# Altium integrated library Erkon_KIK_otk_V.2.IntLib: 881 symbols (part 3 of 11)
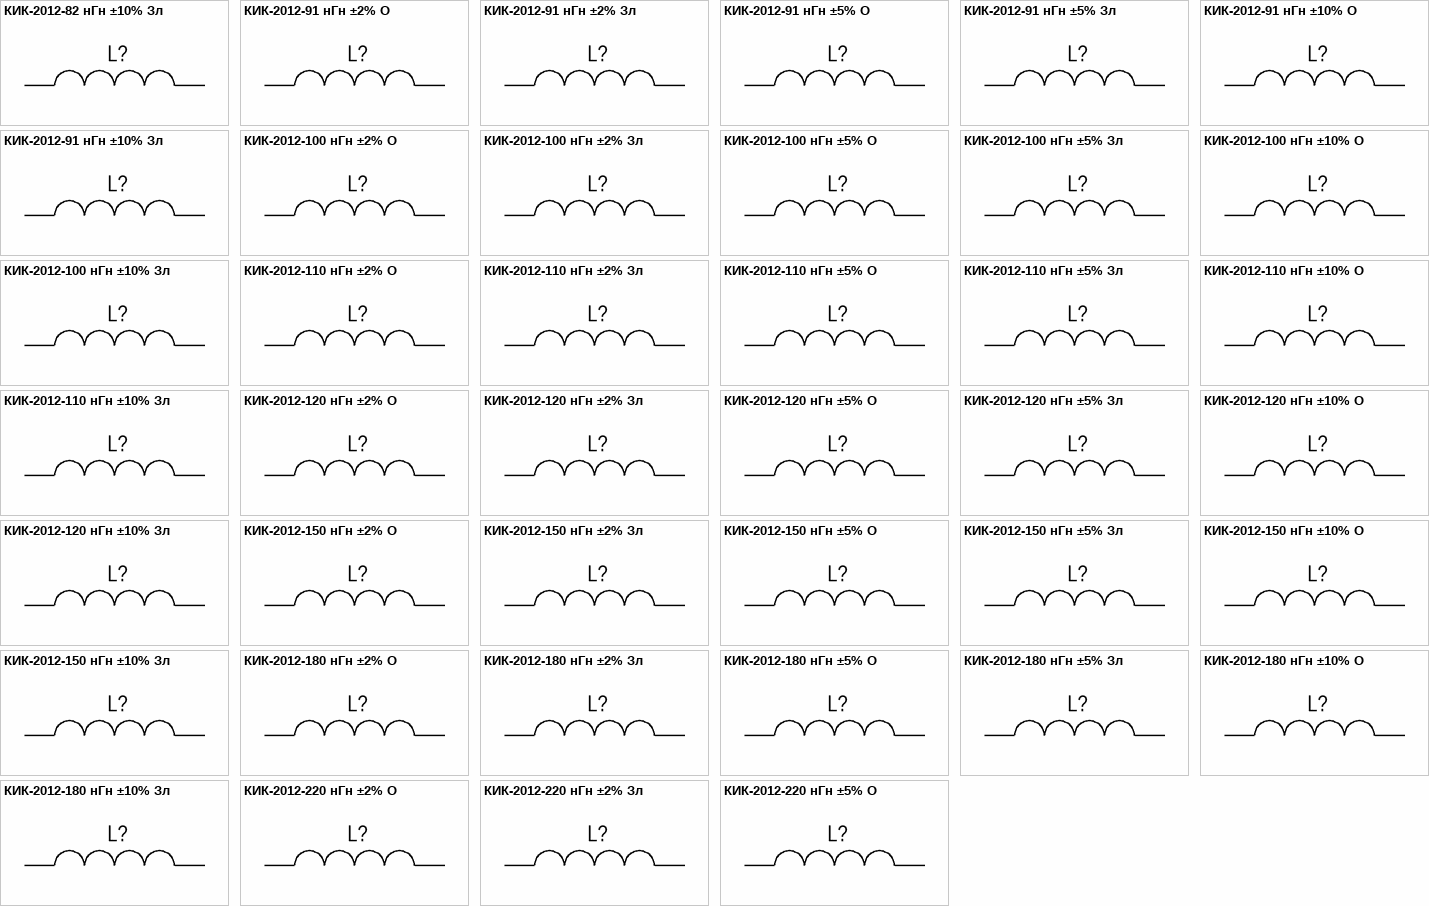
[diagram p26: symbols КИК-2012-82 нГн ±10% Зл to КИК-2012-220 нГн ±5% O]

## КИК-2012-220 нГн ±2% Зл
designator L?, comment 220 нГн ±2%  (value not drawn)
Катушка индуктивности с керамическим сердечником и золотым покрытием контактных площадок; Номиналиная индуктивность: 220 нГн; Добротность, не менее: 50; Резонансная частота, не менее: 0.82 ГГц; Сопротивление обмотки постоянноми току, не более: 0.70 Ом; Допустимый ток обмотки: 400 мА; Диапазон рабочих температур: от -60 до +125 ℃; Упаковка: Катушка и лента; Типоразмер: 2012 (0805); Технология монтажа: SMT; Изготовитель: АО "НПО "ЭРКОН"
footprint КИК-2012-Зл (Катушка индуктивности с керамическим сердечникомтипоразмер 2012(0805))
pins: 1, 2

## КИК-2012-220 нГн ±5% O
designator L?, comment 220 нГн ±5%  (value not drawn)
Катушка индуктивности с керамическим сердечником и  финишным покрытием контактных площадок оловом; Номиналиная индуктивность: 220 нГн; Добротность, не менее: 50; Резонансная частота, не менее: 0.82 ГГц; Сопротивление обмотки постоянноми току, не более: 0.70 Ом; Допустимый ток обмотки: 400 мА; Диапазон рабочих температур: от -60 до +125 ℃; Упаковка: Катушка и лента; Типоразмер: 2012 (0805); Технология монтажа: SMT; Изготовитель: АО "НПО "ЭРКОН"
footprint КИК-2012-O (Катушка индуктивности с керамическим сердечником типоразмер 2012(0805))
pins: 1, 2

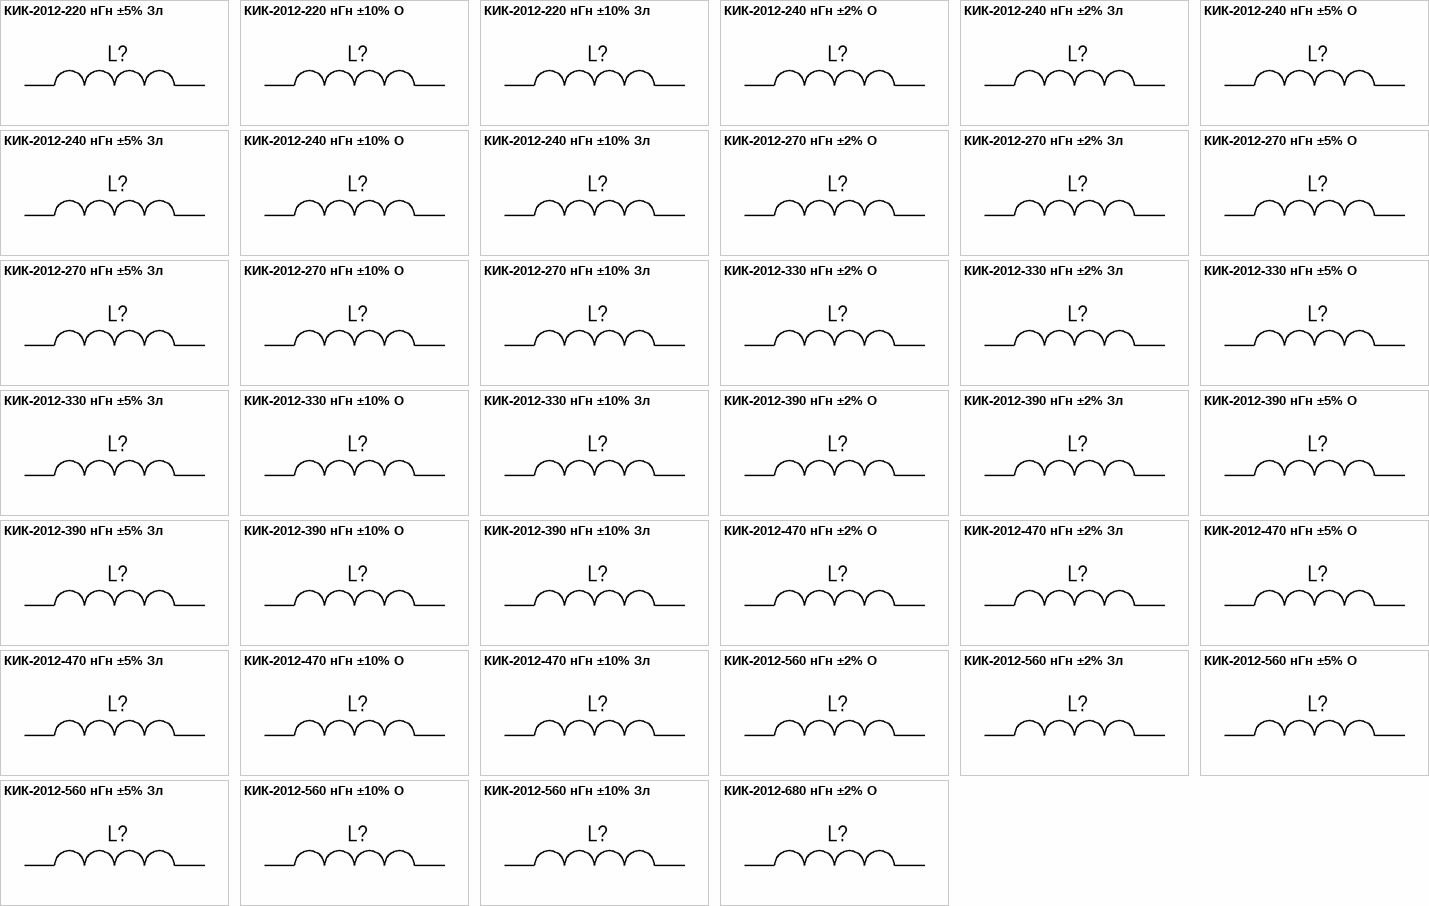
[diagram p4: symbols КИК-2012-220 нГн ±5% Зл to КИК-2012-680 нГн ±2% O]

## КИК-2012-220 нГн ±5% Зл
designator L?, comment 220 нГн ±5%  (value not drawn)
Катушка индуктивности с керамическим сердечником и золотым покрытием контактных площадок; Номиналиная индуктивность: 220 нГн; Добротность, не менее: 50; Резонансная частота, не менее: 0.82 ГГц; Сопротивление обмотки постоянноми току, не более: 0.70 Ом; Допустимый ток обмотки: 400 мА; Диапазон рабочих температур: от -60 до +125 ℃; Упаковка: Катушка и лента; Типоразмер: 2012 (0805); Технология монтажа: SMT; Изготовитель: АО "НПО "ЭРКОН"
footprint КИК-2012-Зл (Катушка индуктивности с керамическим сердечникомтипоразмер 2012(0805))
pins: 1, 2

## КИК-2012-220 нГн ±10% O
designator L?, comment 220 нГн ±10%  (value not drawn)
Катушка индуктивности с керамическим сердечником и  финишным покрытием контактных площадок оловом; Номиналиная индуктивность: 220 нГн; Добротность, не менее: 50; Резонансная частота, не менее: 0.82 ГГц; Сопротивление обмотки постоянноми току, не более: 0.70 Ом; Допустимый ток обмотки: 400 мА; Диапазон рабочих температур: от -60 до +125 ℃; Упаковка: Катушка и лента; Типоразмер: 2012 (0805); Технология монтажа: SMT; Изготовитель: АО "НПО "ЭРКОН"
footprint КИК-2012-O (Катушка индуктивности с керамическим сердечником типоразмер 2012(0805))
pins: 1, 2

## КИК-2012-220 нГн ±10% Зл
designator L?, comment 220 нГн ±10%  (value not drawn)
Катушка индуктивности с керамическим сердечником и золотым покрытием контактных площадок; Номиналиная индуктивность: 220 нГн; Добротность, не менее: 50; Резонансная частота, не менее: 0.82 ГГц; Сопротивление обмотки постоянноми току, не более: 0.70 Ом; Допустимый ток обмотки: 400 мА; Диапазон рабочих температур: от -60 до +125 ℃; Упаковка: Катушка и лента; Типоразмер: 2012 (0805); Технология монтажа: SMT; Изготовитель: АО "НПО "ЭРКОН"
footprint КИК-2012-Зл (Катушка индуктивности с керамическим сердечникомтипоразмер 2012(0805))
pins: 1, 2

## КИК-2012-240 нГн ±2% O
designator L?, comment 240 нГн ±2%  (value not drawn)
Катушка индуктивности с керамическим сердечником и  финишным покрытием контактных площадок оловом; Номиналиная индуктивность: 240 нГн; Добротность, не менее: 45; Резонансная частота, не менее: 0.77 ГГц; Сопротивление обмотки постоянноми току, не более: 1.0 Ом; Допустимый ток обмотки: 350 мА; Диапазон рабочих температур: от -60 до +125 ℃; Упаковка: Катушка и лента; Типоразмер: 2012 (0805); Технология монтажа: SMT; Изготовитель: АО "НПО "ЭРКОН"
footprint КИК-2012-O (Катушка индуктивности с керамическим сердечником типоразмер 2012(0805))
pins: 1, 2

## КИК-2012-240 нГн ±2% Зл
designator L?, comment 240 нГн ±2%  (value not drawn)
Катушка индуктивности с керамическим сердечником и золотым покрытием контактных площадок; Номиналиная индуктивность: 240 нГн; Добротность, не менее: 45; Резонансная частота, не менее: 0.77 ГГц; Сопротивление обмотки постоянноми току, не более: 1.0 Ом; Допустимый ток обмотки: 350 мА; Диапазон рабочих температур: от -60 до +125 ℃; Упаковка: Катушка и лента; Типоразмер: 2012 (0805); Технология монтажа: SMT; Изготовитель: АО "НПО "ЭРКОН"
footprint КИК-2012-Зл (Катушка индуктивности с керамическим сердечникомтипоразмер 2012(0805))
pins: 1, 2

## КИК-2012-240 нГн ±5% O
designator L?, comment 240 нГн ±5%  (value not drawn)
Катушка индуктивности с керамическим сердечником и  финишным покрытием контактных площадок оловом; Номиналиная индуктивность: 240 нГн; Добротность, не менее: 45; Резонансная частота, не менее: 0.77 ГГц; Сопротивление обмотки постоянноми току, не более: 1.0 Ом; Допустимый ток обмотки: 350 мА; Диапазон рабочих температур: от -60 до +125 ℃; Упаковка: Катушка и лента; Типоразмер: 2012 (0805); Технология монтажа: SMT; Изготовитель: АО "НПО "ЭРКОН"
footprint КИК-2012-O (Катушка индуктивности с керамическим сердечником типоразмер 2012(0805))
pins: 1, 2

## КИК-2012-240 нГн ±5% Зл
designator L?, comment 240 нГн ±5%  (value not drawn)
Катушка индуктивности с керамическим сердечником и золотым покрытием контактных площадок; Номиналиная индуктивность: 240 нГн; Добротность, не менее: 45; Резонансная частота, не менее: 0.77 ГГц; Сопротивление обмотки постоянноми току, не более: 1.0 Ом; Допустимый ток обмотки: 350 мА; Диапазон рабочих температур: от -60 до +125 ℃; Упаковка: Катушка и лента; Типоразмер: 2012 (0805); Технология монтажа: SMT; Изготовитель: АО "НПО "ЭРКОН"
footprint КИК-2012-Зл (Катушка индуктивности с керамическим сердечникомтипоразмер 2012(0805))
pins: 1, 2

## КИК-2012-240 нГн ±10% O
designator L?, comment 240 нГн ±10%  (value not drawn)
Катушка индуктивности с керамическим сердечником и  финишным покрытием контактных площадок оловом; Номиналиная индуктивность: 240 нГн; Добротность, не менее: 45; Резонансная частота, не менее: 0.77 ГГц; Сопротивление обмотки постоянноми току, не более: 1.0 Ом; Допустимый ток обмотки: 350 мА; Диапазон рабочих температур: от -60 до +125 ℃; Упаковка: Катушка и лента; Типоразмер: 2012 (0805); Технология монтажа: SMT; Изготовитель: АО "НПО "ЭРКОН"
footprint КИК-2012-O (Катушка индуктивности с керамическим сердечником типоразмер 2012(0805))
pins: 1, 2

## КИК-2012-240 нГн ±10% Зл
designator L?, comment 240 нГн ±10%  (value not drawn)
Катушка индуктивности с керамическим сердечником и золотым покрытием контактных площадок; Номиналиная индуктивность: 240 нГн; Добротность, не менее: 45; Резонансная частота, не менее: 0.77 ГГц; Сопротивление обмотки постоянноми току, не более: 1.0 Ом; Допустимый ток обмотки: 350 мА; Диапазон рабочих температур: от -60 до +125 ℃; Упаковка: Катушка и лента; Типоразмер: 2012 (0805); Технология монтажа: SMT; Изготовитель: АО "НПО "ЭРКОН"
footprint КИК-2012-Зл (Катушка индуктивности с керамическим сердечникомтипоразмер 2012(0805))
pins: 1, 2

## КИК-2012-270 нГн ±2% O
designator L?, comment 270 нГн ±2%  (value not drawn)
Катушка индуктивности с керамическим сердечником и  финишным покрытием контактных площадок оловом; Номиналиная индуктивность: 270 нГн; Добротность, не менее: 45; Резонансная частота, не менее: 0.73 ГГц; Сопротивление обмотки постоянноми току, не более: 1.0 Ом; Допустимый ток обмотки: 350 мА; Диапазон рабочих температур: от -60 до +125 ℃; Упаковка: Катушка и лента; Типоразмер: 2012 (0805); Технология монтажа: SMT; Изготовитель: АО "НПО "ЭРКОН"
footprint КИК-2012-O (Катушка индуктивности с керамическим сердечником типоразмер 2012(0805))
pins: 1, 2

## КИК-2012-270 нГн ±2% Зл
designator L?, comment 270 нГн ±2%  (value not drawn)
Катушка индуктивности с керамическим сердечником и золотым покрытием контактных площадок; Номиналиная индуктивность: 270 нГн; Добротность, не менее: 45; Резонансная частота, не менее: 0.73 ГГц; Сопротивление обмотки постоянноми току, не более: 1.0 Ом; Допустимый ток обмотки: 350 мА; Диапазон рабочих температур: от -60 до +125 ℃; Упаковка: Катушка и лента; Типоразмер: 2012 (0805); Технология монтажа: SMT; Изготовитель: АО "НПО "ЭРКОН"
footprint КИК-2012-Зл (Катушка индуктивности с керамическим сердечникомтипоразмер 2012(0805))
pins: 1, 2

## КИК-2012-270 нГн ±5% O
designator L?, comment 270 нГн ±5%  (value not drawn)
Катушка индуктивности с керамическим сердечником и  финишным покрытием контактных площадок оловом; Номиналиная индуктивность: 270 нГн; Добротность, не менее: 45; Резонансная частота, не менее: 0.73 ГГц; Сопротивление обмотки постоянноми току, не более: 1.0 Ом; Допустимый ток обмотки: 350 мА; Диапазон рабочих температур: от -60 до +125 ℃; Упаковка: Катушка и лента; Типоразмер: 2012 (0805); Технология монтажа: SMT; Изготовитель: АО "НПО "ЭРКОН"
footprint КИК-2012-O (Катушка индуктивности с керамическим сердечником типоразмер 2012(0805))
pins: 1, 2

## КИК-2012-270 нГн ±5% Зл
designator L?, comment 270 нГн ±5%  (value not drawn)
Катушка индуктивности с керамическим сердечником и золотым покрытием контактных площадок; Номиналиная индуктивность: 270 нГн; Добротность, не менее: 45; Резонансная частота, не менее: 0.73 ГГц; Сопротивление обмотки постоянноми току, не более: 1.0 Ом; Допустимый ток обмотки: 350 мА; Диапазон рабочих температур: от -60 до +125 ℃; Упаковка: Катушка и лента; Типоразмер: 2012 (0805); Технология монтажа: SMT; Изготовитель: АО "НПО "ЭРКОН"
footprint КИК-2012-Зл (Катушка индуктивности с керамическим сердечникомтипоразмер 2012(0805))
pins: 1, 2

## КИК-2012-270 нГн ±10% O
designator L?, comment 270 нГн ±10%  (value not drawn)
Катушка индуктивности с керамическим сердечником и  финишным покрытием контактных площадок оловом; Номиналиная индуктивность: 270 нГн; Добротность, не менее: 45; Резонансная частота, не менее: 0.73 ГГц; Сопротивление обмотки постоянноми току, не более: 1.0 Ом; Допустимый ток обмотки: 350 мА; Диапазон рабочих температур: от -60 до +125 ℃; Упаковка: Катушка и лента; Типоразмер: 2012 (0805); Технология монтажа: SMT; Изготовитель: АО "НПО "ЭРКОН"
footprint КИК-2012-O (Катушка индуктивности с керамическим сердечником типоразмер 2012(0805))
pins: 1, 2

## КИК-2012-270 нГн ±10% Зл
designator L?, comment 270 нГн ±10%  (value not drawn)
Катушка индуктивности с керамическим сердечником и золотым покрытием контактных площадок; Номиналиная индуктивность: 270 нГн; Добротность, не менее: 45; Резонансная частота, не менее: 0.73 ГГц; Сопротивление обмотки постоянноми току, не более: 1.0 Ом; Допустимый ток обмотки: 350 мА; Диапазон рабочих температур: от -60 до +125 ℃; Упаковка: Катушка и лента; Типоразмер: 2012 (0805); Технология монтажа: SMT; Изготовитель: АО "НПО "ЭРКОН"
footprint КИК-2012-Зл (Катушка индуктивности с керамическим сердечникомтипоразмер 2012(0805))
pins: 1, 2

## КИК-2012-330 нГн ±2% O
designator L?, comment 330 нГн ±2%  (value not drawn)
Катушка индуктивности с керамическим сердечником и  финишным покрытием контактных площадок оловом; Номиналиная индуктивность: 330 нГн; Добротность, не менее: 45; Резонансная частота, не менее: 0.65 ГГц; Сопротивление обмотки постоянноми току, не более: 1.4 Ом; Допустимый ток обмотки: 310 мА; Диапазон рабочих температур: от -60 до +125 ℃; Упаковка: Катушка и лента; Типоразмер: 2012 (0805); Технология монтажа: SMT; Изготовитель: АО "НПО "ЭРКОН"
footprint КИК-2012-O (Катушка индуктивности с керамическим сердечником типоразмер 2012(0805))
pins: 1, 2

## КИК-2012-330 нГн ±2% Зл
designator L?, comment 330 нГн ±2%  (value not drawn)
Катушка индуктивности с керамическим сердечником и золотым покрытием контактных площадок; Номиналиная индуктивность: 330 нГн; Добротность, не менее: 45; Резонансная частота, не менее: 0.65 ГГц; Сопротивление обмотки постоянноми току, не более: 1.4 Ом; Допустимый ток обмотки: 310 мА; Диапазон рабочих температур: от -60 до +125 ℃; Упаковка: Катушка и лента; Типоразмер: 2012 (0805); Технология монтажа: SMT; Изготовитель: АО "НПО "ЭРКОН"
footprint КИК-2012-Зл (Катушка индуктивности с керамическим сердечникомтипоразмер 2012(0805))
pins: 1, 2

## КИК-2012-330 нГн ±5% O
designator L?, comment 330 нГн ±5%  (value not drawn)
Катушка индуктивности с керамическим сердечником и  финишным покрытием контактных площадок оловом; Номиналиная индуктивность: 330 нГн; Добротность, не менее: 45; Резонансная частота, не менее: 0.65 ГГц; Сопротивление обмотки постоянноми току, не более: 1.4 Ом; Допустимый ток обмотки: 310 мА; Диапазон рабочих температур: от -60 до +125 ℃; Упаковка: Катушка и лента; Типоразмер: 2012 (0805); Технология монтажа: SMT; Изготовитель: АО "НПО "ЭРКОН"
footprint КИК-2012-O (Катушка индуктивности с керамическим сердечником типоразмер 2012(0805))
pins: 1, 2

## КИК-2012-330 нГн ±5% Зл
designator L?, comment 330 нГн ±5%  (value not drawn)
Катушка индуктивности с керамическим сердечником и золотым покрытием контактных площадок; Номиналиная индуктивность: 330 нГн; Добротность, не менее: 45; Резонансная частота, не менее: 0.65 ГГц; Сопротивление обмотки постоянноми току, не более: 1.4 Ом; Допустимый ток обмотки: 310 мА; Диапазон рабочих температур: от -60 до +125 ℃; Упаковка: Катушка и лента; Типоразмер: 2012 (0805); Технология монтажа: SMT; Изготовитель: АО "НПО "ЭРКОН"
footprint КИК-2012-Зл (Катушка индуктивности с керамическим сердечникомтипоразмер 2012(0805))
pins: 1, 2

## КИК-2012-330 нГн ±10% O
designator L?, comment 330 нГн ±10%  (value not drawn)
Катушка индуктивности с керамическим сердечником и  финишным покрытием контактных площадок оловом; Номиналиная индуктивность: 330 нГн; Добротность, не менее: 45; Резонансная частота, не менее: 0.65 ГГц; Сопротивление обмотки постоянноми току, не более: 1.4 Ом; Допустимый ток обмотки: 310 мА; Диапазон рабочих температур: от -60 до +125 ℃; Упаковка: Катушка и лента; Типоразмер: 2012 (0805); Технология монтажа: SMT; Изготовитель: АО "НПО "ЭРКОН"
footprint КИК-2012-O (Катушка индуктивности с керамическим сердечником типоразмер 2012(0805))
pins: 1, 2

## КИК-2012-330 нГн ±10% Зл
designator L?, comment 330 нГн ±10%  (value not drawn)
Катушка индуктивности с керамическим сердечником и золотым покрытием контактных площадок; Номиналиная индуктивность: 330 нГн; Добротность, не менее: 45; Резонансная частота, не менее: 0.65 ГГц; Сопротивление обмотки постоянноми току, не более: 1.4 Ом; Допустимый ток обмотки: 310 мА; Диапазон рабочих температур: от -60 до +125 ℃; Упаковка: Катушка и лента; Типоразмер: 2012 (0805); Технология монтажа: SMT; Изготовитель: АО "НПО "ЭРКОН"
footprint КИК-2012-Зл (Катушка индуктивности с керамическим сердечникомтипоразмер 2012(0805))
pins: 1, 2

## КИК-2012-390 нГн ±2% O
designator L?, comment 390 нГн ±2%  (value not drawn)
Катушка индуктивности с керамическим сердечником и  финишным покрытием контактных площадок оловом; Номиналиная индуктивность: 390 нГн; Добротность, не менее: 45; Резонансная частота, не менее: 0.60 ГГц; Сопротивление обмотки постоянноми току, не более: 1.5 Ом; Допустимый ток обмотки: 290 мА; Диапазон рабочих температур: от -60 до +125 ℃; Упаковка: Катушка и лента; Типоразмер: 2012 (0805); Технология монтажа: SMT; Изготовитель: АО "НПО "ЭРКОН"
footprint КИК-2012-O (Катушка индуктивности с керамическим сердечником типоразмер 2012(0805))
pins: 1, 2

## КИК-2012-390 нГн ±2% Зл
designator L?, comment 390 нГн ±2%  (value not drawn)
Катушка индуктивности с керамическим сердечником и золотым покрытием контактных площадок; Номиналиная индуктивность: 390 нГн; Добротность, не менее: 45; Резонансная частота, не менее: 0.60 ГГц; Сопротивление обмотки постоянноми току, не более: 1.5 Ом; Допустимый ток обмотки: 290 мА; Диапазон рабочих температур: от -60 до +125 ℃; Упаковка: Катушка и лента; Типоразмер: 2012 (0805); Технология монтажа: SMT; Изготовитель: АО "НПО "ЭРКОН"
footprint КИК-2012-Зл (Катушка индуктивности с керамическим сердечникомтипоразмер 2012(0805))
pins: 1, 2

## КИК-2012-390 нГн ±5% O
designator L?, comment 390 нГн ±5%  (value not drawn)
Катушка индуктивности с керамическим сердечником и  финишным покрытием контактных площадок оловом; Номиналиная индуктивность: 390 нГн; Добротность, не менее: 45; Резонансная частота, не менее: 0.60 ГГц; Сопротивление обмотки постоянноми току, не более: 1.5 Ом; Допустимый ток обмотки: 290 мА; Диапазон рабочих температур: от -60 до +125 ℃; Упаковка: Катушка и лента; Типоразмер: 2012 (0805); Технология монтажа: SMT; Изготовитель: АО "НПО "ЭРКОН"
footprint КИК-2012-O (Катушка индуктивности с керамическим сердечником типоразмер 2012(0805))
pins: 1, 2

## КИК-2012-390 нГн ±5% Зл
designator L?, comment 390 нГн ±5%  (value not drawn)
Катушка индуктивности с керамическим сердечником и золотым покрытием контактных площадок; Номиналиная индуктивность: 390 нГн; Добротность, не менее: 45; Резонансная частота, не менее: 0.60 ГГц; Сопротивление обмотки постоянноми току, не более: 1.5 Ом; Допустимый ток обмотки: 290 мА; Диапазон рабочих температур: от -60 до +125 ℃; Упаковка: Катушка и лента; Типоразмер: 2012 (0805); Технология монтажа: SMT; Изготовитель: АО "НПО "ЭРКОН"
footprint КИК-2012-Зл (Катушка индуктивности с керамическим сердечникомтипоразмер 2012(0805))
pins: 1, 2

## КИК-2012-390 нГн ±10% O
designator L?, comment 390 нГн ±10%  (value not drawn)
Катушка индуктивности с керамическим сердечником и  финишным покрытием контактных площадок оловом; Номиналиная индуктивность: 390 нГн; Добротность, не менее: 45; Резонансная частота, не менее: 0.60 ГГц; Сопротивление обмотки постоянноми току, не более: 1.5 Ом; Допустимый ток обмотки: 290 мА; Диапазон рабочих температур: от -60 до +125 ℃; Упаковка: Катушка и лента; Типоразмер: 2012 (0805); Технология монтажа: SMT; Изготовитель: АО "НПО "ЭРКОН"
footprint КИК-2012-O (Катушка индуктивности с керамическим сердечником типоразмер 2012(0805))
pins: 1, 2

## КИК-2012-390 нГн ±10% Зл
designator L?, comment 390 нГн ±10%  (value not drawn)
Катушка индуктивности с керамическим сердечником и золотым покрытием контактных площадок; Номиналиная индуктивность: 390 нГн; Добротность, не менее: 45; Резонансная частота, не менее: 0.60 ГГц; Сопротивление обмотки постоянноми току, не более: 1.5 Ом; Допустимый ток обмотки: 290 мА; Диапазон рабочих температур: от -60 до +125 ℃; Упаковка: Катушка и лента; Типоразмер: 2012 (0805); Технология монтажа: SMT; Изготовитель: АО "НПО "ЭРКОН"
footprint КИК-2012-Зл (Катушка индуктивности с керамическим сердечникомтипоразмер 2012(0805))
pins: 1, 2

## КИК-2012-470 нГн ±2% O
designator L?, comment 470 нГн ±2%  (value not drawn)
Катушка индуктивности с керамическим сердечником и  финишным покрытием контактных площадок оловом; Номиналиная индуктивность: 470 нГн; Добротность, не менее: 33; Резонансная частота, не менее: 0.375 ГГц; Сопротивление обмотки постоянноми току, не более: 1.76 Ом; Допустимый ток обмотки: 250 мА; Диапазон рабочих температур: от -60 до +125 ℃; Упаковка: Катушка и лента; Типоразмер: 2012 (0805); Технология монтажа: SMT; Изготовитель: АО "НПО "ЭРКОН"
footprint КИК-2012-O (Катушка индуктивности с керамическим сердечником типоразмер 2012(0805))
pins: 1, 2

## КИК-2012-470 нГн ±2% Зл
designator L?, comment 470 нГн ±2%  (value not drawn)
Катушка индуктивности с керамическим сердечником и золотым покрытием контактных площадок; Номиналиная индуктивность: 470 нГн; Добротность, не менее: 33; Резонансная частота, не менее: 0.375 ГГц; Сопротивление обмотки постоянноми току, не более: 1.76 Ом; Допустимый ток обмотки: 250 мА; Диапазон рабочих температур: от -60 до +125 ℃; Упаковка: Катушка и лента; Типоразмер: 2012 (0805); Технология монтажа: SMT; Изготовитель: АО "НПО "ЭРКОН"
footprint КИК-2012-Зл (Катушка индуктивности с керамическим сердечникомтипоразмер 2012(0805))
pins: 1, 2

## КИК-2012-470 нГн ±5% O
designator L?, comment 470 нГн ±5%  (value not drawn)
Катушка индуктивности с керамическим сердечником и  финишным покрытием контактных площадок оловом; Номиналиная индуктивность: 470 нГн; Добротность, не менее: 33; Резонансная частота, не менее: 0.375 ГГц; Сопротивление обмотки постоянноми току, не более: 1.76 Ом; Допустимый ток обмотки: 250 мА; Диапазон рабочих температур: от -60 до +125 ℃; Упаковка: Катушка и лента; Типоразмер: 2012 (0805); Технология монтажа: SMT; Изготовитель: АО "НПО "ЭРКОН"
footprint КИК-2012-O (Катушка индуктивности с керамическим сердечником типоразмер 2012(0805))
pins: 1, 2

## КИК-2012-470 нГн ±5% Зл
designator L?, comment 470 нГн ±5%  (value not drawn)
Катушка индуктивности с керамическим сердечником и золотым покрытием контактных площадок; Номиналиная индуктивность: 470 нГн; Добротность, не менее: 33; Резонансная частота, не менее: 0.375 ГГц; Сопротивление обмотки постоянноми току, не более: 1.76 Ом; Допустимый ток обмотки: 250 мА; Диапазон рабочих температур: от -60 до +125 ℃; Упаковка: Катушка и лента; Типоразмер: 2012 (0805); Технология монтажа: SMT; Изготовитель: АО "НПО "ЭРКОН"
footprint КИК-2012-Зл (Катушка индуктивности с керамическим сердечникомтипоразмер 2012(0805))
pins: 1, 2

## КИК-2012-470 нГн ±10% O
designator L?, comment 470 нГн ±10%  (value not drawn)
Катушка индуктивности с керамическим сердечником и  финишным покрытием контактных площадок оловом; Номиналиная индуктивность: 470 нГн; Добротность, не менее: 33; Резонансная частота, не менее: 0.375 ГГц; Сопротивление обмотки постоянноми току, не более: 1.76 Ом; Допустимый ток обмотки: 250 мА; Диапазон рабочих температур: от -60 до +125 ℃; Упаковка: Катушка и лента; Типоразмер: 2012 (0805); Технология монтажа: SMT; Изготовитель: АО "НПО "ЭРКОН"
footprint КИК-2012-O (Катушка индуктивности с керамическим сердечником типоразмер 2012(0805))
pins: 1, 2

## КИК-2012-470 нГн ±10% Зл
designator L?, comment 470 нГн ±10%  (value not drawn)
Катушка индуктивности с керамическим сердечником и золотым покрытием контактных площадок; Номиналиная индуктивность: 470 нГн; Добротность, не менее: 33; Резонансная частота, не менее: 0.375 ГГц; Сопротивление обмотки постоянноми току, не более: 1.76 Ом; Допустимый ток обмотки: 250 мА; Диапазон рабочих температур: от -60 до +125 ℃; Упаковка: Катушка и лента; Типоразмер: 2012 (0805); Технология монтажа: SMT; Изготовитель: АО "НПО "ЭРКОН"
footprint КИК-2012-Зл (Катушка индуктивности с керамическим сердечникомтипоразмер 2012(0805))
pins: 1, 2

## КИК-2012-560 нГн ±2% O
designator L?, comment 560 нГн ±2%  (value not drawn)
Катушка индуктивности с керамическим сердечником и  финишным покрытием контактных площадок оловом; Номиналиная индуктивность: 560 нГн; Добротность, не менее: 23; Резонансная частота, не менее: 0.330 ГГц; Сопротивление обмотки постоянноми току, не более: 1.9 Ом; Допустимый ток обмотки: 230 мА; Диапазон рабочих температур: от -60 до +125 ℃; Упаковка: Катушка и лента; Типоразмер: 2012 (0805); Технология монтажа: SMT; Изготовитель: АО "НПО "ЭРКОН"
footprint КИК-2012-O (Катушка индуктивности с керамическим сердечником типоразмер 2012(0805))
pins: 1, 2

## КИК-2012-560 нГн ±2% Зл
designator L?, comment 560 нГн ±5%  (value not drawn)
Катушка индуктивности с керамическим сердечником и золотым покрытием контактных площадок; Номиналиная индуктивность: 560 нГн; Допускаемое отклонение индуктивности: ±2%; Добротность, не менее: 23; Резонансная частота, не менее: 0.330 ГГц; Сопротивление обмотки постоянноми току, не более: 1.9 Ом; Допустимый ток обмотки: 230 мА; Диапазон рабочих температур: от -60 до +125 ℃; Упаковка: Катушка и лента; Типоразмер: 2012 (0805); Технология монтажа: SMT; Изготовитель: АО "НПО "ЭРКОН"
footprint КИК-2012-Зл (Катушка индуктивности с керамическим сердечникомтипоразмер 2012(0805))
pins: 1, 2

## КИК-2012-560 нГн ±5% O
designator L?, comment 560 нГн ±5%  (value not drawn)
Катушка индуктивности с керамическим сердечником и  финишным покрытием контактных площадок оловом; Номиналиная индуктивность: 560 нГн; Добротность, не менее: 23; Резонансная частота, не менее: 0.330 ГГц; Сопротивление обмотки постоянноми току, не более: 1.9 Ом; Допустимый ток обмотки: 230 мА; Диапазон рабочих температур: от -60 до +125 ℃; Упаковка: Катушка и лента; Типоразмер: 2012 (0805); Технология монтажа: SMT; Изготовитель: АО "НПО "ЭРКОН"
footprint КИК-2012-O (Катушка индуктивности с керамическим сердечником типоразмер 2012(0805))
pins: 1, 2

## КИК-2012-560 нГн ±5% Зл
designator L?, comment 560 нГн ±5%  (value not drawn)
Катушка индуктивности с керамическим сердечником и золотым покрытием контактных площадок; Номиналиная индуктивность: 560 нГн; Добротность, не менее: 23; Резонансная частота, не менее: 0.330 ГГц; Сопротивление обмотки постоянноми току, не более: 1.9 Ом; Допустимый ток обмотки: 230 мА; Диапазон рабочих температур: от -60 до +125 ℃; Упаковка: Катушка и лента; Типоразмер: 2012 (0805); Технология монтажа: SMT; Изготовитель: АО "НПО "ЭРКОН"
footprint КИК-2012-Зл (Катушка индуктивности с керамическим сердечникомтипоразмер 2012(0805))
pins: 1, 2

## КИК-2012-560 нГн ±10% O
designator L?, comment 560 нГн ±10%  (value not drawn)
Катушка индуктивности с керамическим сердечником и  финишным покрытием контактных площадок оловом; Номиналиная индуктивность: 560 нГн; Добротность, не менее: 23; Резонансная частота, не менее: 0.330 ГГц; Сопротивление обмотки постоянноми току, не более: 1.9 Ом; Допустимый ток обмотки: 230 мА; Диапазон рабочих температур: от -60 до +125 ℃; Упаковка: Катушка и лента; Типоразмер: 2012 (0805); Технология монтажа: SMT; Изготовитель: АО "НПО "ЭРКОН"
footprint КИК-2012-O (Катушка индуктивности с керамическим сердечником типоразмер 2012(0805))
pins: 1, 2

## КИК-2012-560 нГн ±10% Зл
designator L?, comment 560 нГн ±10%  (value not drawn)
Катушка индуктивности с керамическим сердечником и золотым покрытием контактных площадок; Номиналиная индуктивность: 560 нГн; Добротность, не менее: 23; Резонансная частота, не менее: 0.330 ГГц; Сопротивление обмотки постоянноми току, не более: 1.9 Ом; Допустимый ток обмотки: 230 мА; Диапазон рабочих температур: от -60 до +125 ℃; Упаковка: Катушка и лента; Типоразмер: 2012 (0805); Технология монтажа: SMT; Изготовитель: АО "НПО "ЭРКОН"
footprint КИК-2012-Зл (Катушка индуктивности с керамическим сердечникомтипоразмер 2012(0805))
pins: 1, 2

## КИК-2012-680 нГн ±2% O
designator L?, comment 680 нГн ±2%  (value not drawn)
Катушка индуктивности с керамическим сердечником и  финишным покрытием контактных площадок оловом; Номиналиная индуктивность: 680 нГн; Добротность, не менее: 23; Резонансная частота, не менее: 0.31 ГГц; Сопротивление обмотки постоянноми току, не более: 2.2 Ом; Допустимый ток обмотки: 190 мА; Диапазон рабочих температур: от -60 до +125 ℃; Упаковка: Катушка и лента; Типоразмер: 2012 (0805); Технология монтажа: SMT; Изготовитель: АО "НПО "ЭРКОН"
footprint КИК-2012-O (Катушка индуктивности с керамическим сердечником типоразмер 2012(0805))
pins: 1, 2

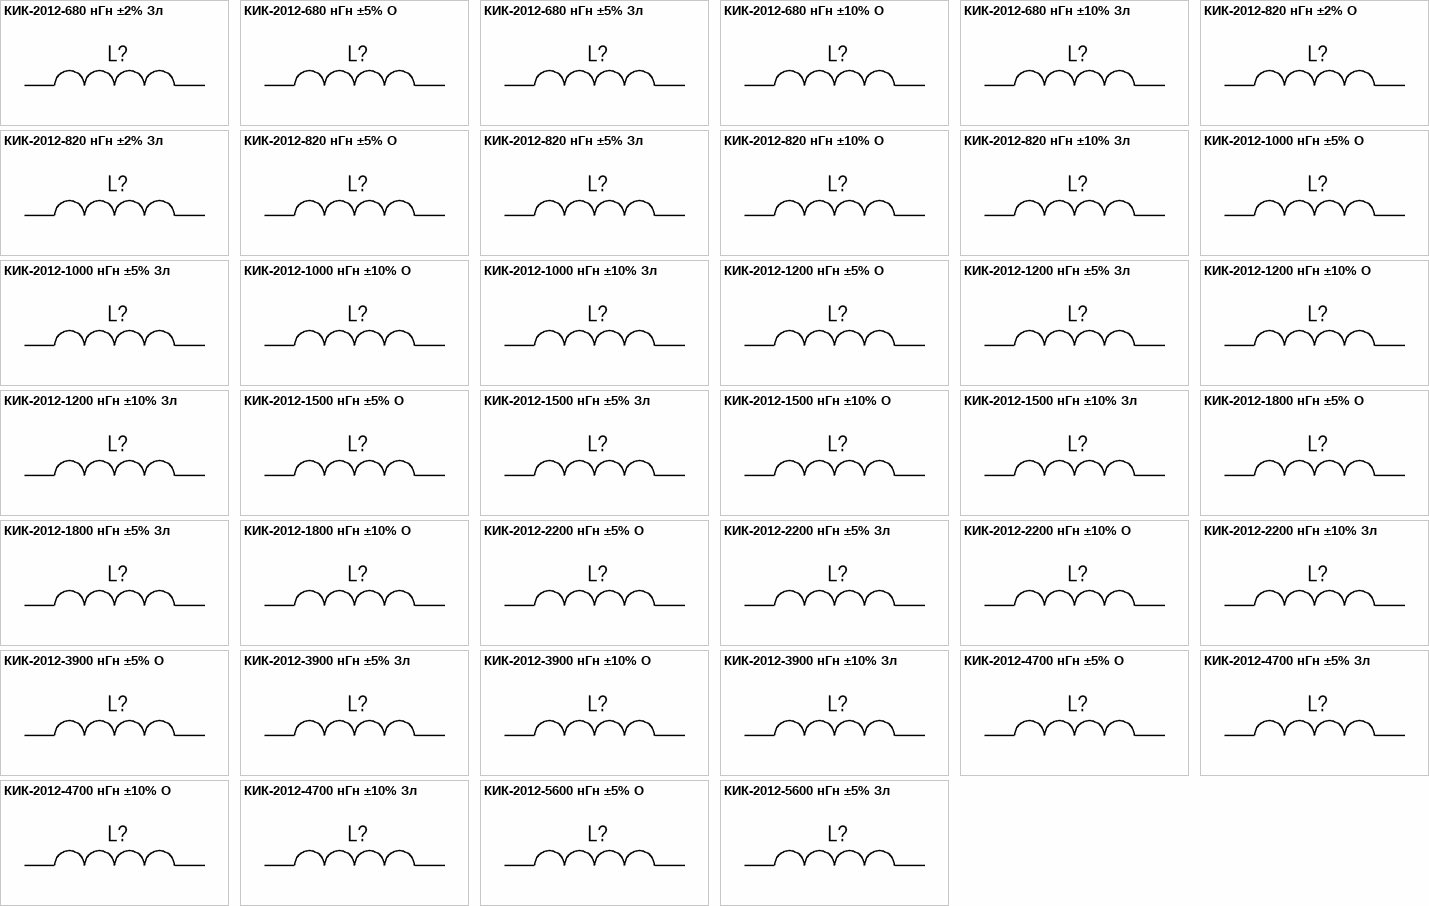
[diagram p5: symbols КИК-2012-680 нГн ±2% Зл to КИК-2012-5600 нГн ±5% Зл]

## КИК-2012-680 нГн ±2% Зл
designator L?, comment 680 нГн ±2%  (value not drawn)
Катушка индуктивности с керамическим сердечником и золотым покрытием контактных площадок; Номиналиная индуктивность: 680 нГн; Добротность, не менее: 23; Резонансная частота, не менее: 0.31 ГГц; Сопротивление обмотки постоянноми току, не более: 2.2 Ом; Допустимый ток обмотки: 190 мА; Диапазон рабочих температур: от -60 до +125 ℃; Упаковка: Катушка и лента; Типоразмер: 2012 (0805); Технология монтажа: SMT; Изготовитель: АО "НПО "ЭРКОН"
footprint КИК-2012-Зл (Катушка индуктивности с керамическим сердечникомтипоразмер 2012(0805))
pins: 1, 2

## КИК-2012-680 нГн ±5% O
designator L?, comment 680 нГн ±5%  (value not drawn)
Катушка индуктивности с керамическим сердечником и  финишным покрытием контактных площадок оловом; Номиналиная индуктивность: 680 нГн; Добротность, не менее: 23; Резонансная частота, не менее: 0.31 ГГц; Сопротивление обмотки постоянноми току, не более: 2.2 Ом; Допустимый ток обмотки: 190 мА; Диапазон рабочих температур: от -60 до +125 ℃; Упаковка: Катушка и лента; Типоразмер: 2012 (0805); Технология монтажа: SMT; Изготовитель: АО "НПО "ЭРКОН"
footprint КИК-2012-O (Катушка индуктивности с керамическим сердечником типоразмер 2012(0805))
pins: 1, 2

## КИК-2012-680 нГн ±5% Зл
designator L?, comment 680 нГн ±5%  (value not drawn)
Катушка индуктивности с керамическим сердечником и золотым покрытием контактных площадок; Номиналиная индуктивность: 680 нГн; Добротность, не менее: 23; Резонансная частота, не менее: 0.31 ГГц; Сопротивление обмотки постоянноми току, не более: 2.2 Ом; Допустимый ток обмотки: 190 мА; Диапазон рабочих температур: от -60 до +125 ℃; Упаковка: Катушка и лента; Типоразмер: 2012 (0805); Технология монтажа: SMT; Изготовитель: АО "НПО "ЭРКОН"
footprint КИК-2012-Зл (Катушка индуктивности с керамическим сердечникомтипоразмер 2012(0805))
pins: 1, 2

## КИК-2012-680 нГн ±10% O
designator L?, comment 680 нГн ±10%  (value not drawn)
Катушка индуктивности с керамическим сердечником и  финишным покрытием контактных площадок оловом; Номиналиная индуктивность: 680 нГн; Добротность, не менее: 23; Резонансная частота, не менее: 0.31 ГГц; Сопротивление обмотки постоянноми току, не более: 2.2 Ом; Допустимый ток обмотки: 190 мА; Диапазон рабочих температур: от -60 до +125 ℃; Упаковка: Катушка и лента; Типоразмер: 2012 (0805); Технология монтажа: SMT; Изготовитель: АО "НПО "ЭРКОН"
footprint КИК-2012-O (Катушка индуктивности с керамическим сердечником типоразмер 2012(0805))
pins: 1, 2

## КИК-2012-680 нГн ±10% Зл
designator L?, comment 680 нГн ±10%  (value not drawn)
Катушка индуктивности с керамическим сердечником и золотым покрытием контактных площадок; Номиналиная индуктивность: 680 нГн; Добротность, не менее: 23; Резонансная частота, не менее: 0.31 ГГц; Сопротивление обмотки постоянноми току, не более: 2.2 Ом; Допустимый ток обмотки: 190 мА; Диапазон рабочих температур: от -60 до +125 ℃; Упаковка: Катушка и лента; Типоразмер: 2012 (0805); Технология монтажа: SMT; Изготовитель: АО "НПО "ЭРКОН"
footprint КИК-2012-Зл (Катушка индуктивности с керамическим сердечникомтипоразмер 2012(0805))
pins: 1, 2

## КИК-2012-820 нГн ±2% O
designator L?, comment 820 нГн ±2%  (value not drawn)
Катушка индуктивности с керамическим сердечником и  финишным покрытием контактных площадок оловом; Номиналиная индуктивность: 820 нГн; Добротность, не менее: 23; Резонансная частота, не менее: 0.31 ГГц; Сопротивление обмотки постоянноми току, не более: 2.35Ом; Допустимый ток обмотки: 180 мА; Диапазон рабочих температур: от -60 до +125 ℃; Упаковка: Катушка и лента; Типоразмер: 2012 (0805); Технология монтажа: SMT; Изготовитель: АО "НПО "ЭРКОН"
footprint КИК-2012-O (Катушка индуктивности с керамическим сердечником типоразмер 2012(0805))
pins: 1, 2

## КИК-2012-820 нГн ±2% Зл
designator L?, comment 820 нГн ±2%  (value not drawn)
Катушка индуктивности с керамическим сердечником и золотым покрытием контактных площадок; Номиналиная индуктивность: 820 нГн; Добротность, не менее: 23; Резонансная частота, не менее: 0.31 ГГц; Сопротивление обмотки постоянноми току, не более: 2.35Ом; Допустимый ток обмотки: 180 мА; Диапазон рабочих температур: от -60 до +125 ℃; Упаковка: Катушка и лента; Типоразмер: 2012 (0805); Технология монтажа: SMT; Изготовитель: АО "НПО "ЭРКОН"
footprint КИК-2012-Зл (Катушка индуктивности с керамическим сердечникомтипоразмер 2012(0805))
pins: 1, 2

## КИК-2012-820 нГн ±5% O
designator L?, comment 820 нГн ±5%  (value not drawn)
Катушка индуктивности с керамическим сердечником и  финишным покрытием контактных площадок оловом; Номиналиная индуктивность: 820 нГн; Добротность, не менее: 23; Резонансная частота, не менее: 0.31 ГГц; Сопротивление обмотки постоянноми току, не более: 2.35Ом; Допустимый ток обмотки: 180 мА; Диапазон рабочих температур: от -60 до +125 ℃; Упаковка: Катушка и лента; Типоразмер: 2012 (0805); Технология монтажа: SMT; Изготовитель: АО "НПО "ЭРКОН"
footprint КИК-2012-O (Катушка индуктивности с керамическим сердечником типоразмер 2012(0805))
pins: 1, 2

## КИК-2012-820 нГн ±5% Зл
designator L?, comment 820 нГн ±5%  (value not drawn)
Катушка индуктивности с керамическим сердечником и золотым покрытием контактных площадок; Номиналиная индуктивность: 820 нГн; Добротность, не менее: 23; Резонансная частота, не менее: 0.31 ГГц; Сопротивление обмотки постоянноми току, не более: 2.35Ом; Допустимый ток обмотки: 180 мА; Диапазон рабочих температур: от -60 до +125 ℃; Упаковка: Катушка и лента; Типоразмер: 2012 (0805); Технология монтажа: SMT; Изготовитель: АО "НПО "ЭРКОН"
footprint КИК-2012-Зл (Катушка индуктивности с керамическим сердечникомтипоразмер 2012(0805))
pins: 1, 2

## КИК-2012-820 нГн ±10% O
designator L?, comment 820 нГн ±10%  (value not drawn)
Катушка индуктивности с керамическим сердечником и  финишным покрытием контактных площадок оловом; Номиналиная индуктивность: 820 нГн; Добротность, не менее: 23; Резонансная частота, не менее: 0.31 ГГц; Сопротивление обмотки постоянноми току, не более: 2.35Ом; Допустимый ток обмотки: 180 мА; Диапазон рабочих температур: от -60 до +125 ℃; Упаковка: Катушка и лента; Типоразмер: 2012 (0805); Технология монтажа: SMT; Изготовитель: АО "НПО "ЭРКОН"
footprint КИК-2012-O (Катушка индуктивности с керамическим сердечником типоразмер 2012(0805))
pins: 1, 2

## КИК-2012-820 нГн ±10% Зл
designator L?, comment 820 нГн ±10%  (value not drawn)
Катушка индуктивности с керамическим сердечником и золотым покрытием контактных площадок; Номиналиная индуктивность: 820 нГн; Добротность, не менее: 23; Резонансная частота, не менее: 0.31 ГГц; Сопротивление обмотки постоянноми току, не более: 2.35Ом; Допустимый ток обмотки: 180 мА; Диапазон рабочих температур: от -60 до +125 ℃; Упаковка: Катушка и лента; Типоразмер: 2012 (0805); Технология монтажа: SMT; Изготовитель: АО "НПО "ЭРКОН"
footprint КИК-2012-Зл (Катушка индуктивности с керамическим сердечникомтипоразмер 2012(0805))
pins: 1, 2

## КИК-2012-1000 нГн ±5% O
designator L?, comment 1000 нГн ±5%  (value not drawn)
Катушка индуктивности с керамическим сердечником и  финишным покрытием контактных площадок оловом; Добротность, не менее: 25; Резонансная частота, не менее: 0.330 ГГц; Сопротивление обмотки постоянноми току, не более: 2.5 Ом; Допустимый ток обмотки: 150 мА; Диапазон рабочих температур: от -60 до +125 ℃; Упаковка: Катушка и лента; Типоразмер: 2012 (0805); Технология монтажа: SMT; Изготовитель: АО "НПО "ЭРКОН"
footprint КИК-2012-O (Катушка индуктивности с керамическим сердечником типоразмер 2012(0805))
pins: 1, 2

## КИК-2012-1000 нГн ±5% Зл
designator L?, comment 1000 нГн ±5%  (value not drawn)
Катушка индуктивности с керамическим сердечником и золотым покрытием контактных площадок; Добротность, не менее: 25; Резонансная частота, не менее: 0.330 ГГц; Сопротивление обмотки постоянноми току, не более: 2.5 Ом; Допустимый ток обмотки: 150 мА; Диапазон рабочих температур: от -60 до +125 ℃; Упаковка: Катушка и лента; Типоразмер: 2012 (0805); Технология монтажа: SMT; Изготовитель: АО "НПО "ЭРКОН"
footprint КИК-2012-Зл (Катушка индуктивности с керамическим сердечникомтипоразмер 2012(0805))
pins: 1, 2

## КИК-2012-1000 нГн ±10% O
designator L?, comment 1000 нГн ±10%  (value not drawn)
Катушка индуктивности с керамическим сердечником и  финишным покрытием контактных площадок оловом; Добротность, не менее: 25; Резонансная частота, не менее: 0.330 ГГц; Сопротивление обмотки постоянноми току, не более: 2.5 Ом; Допустимый ток обмотки: 150 мА; Диапазон рабочих температур: от -60 до +125 ℃; Упаковка: Катушка и лента; Типоразмер: 2012 (0805); Технология монтажа: SMT; Изготовитель: АО "НПО "ЭРКОН"
footprint КИК-2012-O (Катушка индуктивности с керамическим сердечником типоразмер 2012(0805))
pins: 1, 2

## КИК-2012-1000 нГн ±10% Зл
designator L?, comment 1000 нГн ±10%  (value not drawn)
Катушка индуктивности с керамическим сердечником и золотым покрытием контактных площадок; Добротность, не менее: 25; Резонансная частота, не менее: 0.330 ГГц; Сопротивление обмотки постоянноми току, не более: 2.5 Ом; Допустимый ток обмотки: 150 мА; Диапазон рабочих температур: от -60 до +125 ℃; Упаковка: Катушка и лента; Типоразмер: 2012 (0805); Технология монтажа: SMT; Изготовитель: АО "НПО "ЭРКОН"
footprint КИК-2012-Зл (Катушка индуктивности с керамическим сердечникомтипоразмер 2012(0805))
pins: 1, 2

## КИК-2012-1200 нГн ±5% O
designator L?, comment 1200 нГн ±5%  (value not drawn)
Катушка индуктивности с керамическим сердечником и  финишным покрытием контактных площадок оловом; Добротность, не менее: 17; Резонансная частота, не менее: 0.200 ГГц; Сопротивление обмотки постоянноми току, не более: 2.38 Ом; Допустимый ток обмотки: 150 мА; Диапазон рабочих температур: от -60 до +125 ℃; Упаковка: Катушка и лента; Типоразмер: 2012 (0805); Технология монтажа: SMT; Изготовитель: АО "НПО "ЭРКОН"
footprint КИК-2012-O (Катушка индуктивности с керамическим сердечником типоразмер 2012(0805))
pins: 1, 2

## КИК-2012-1200 нГн ±5% Зл
designator L?, comment 1200 нГн ±5%  (value not drawn)
Катушка индуктивности с керамическим сердечником и золотым покрытием контактных площадок; Добротность, не менее: 17; Резонансная частота, не менее: 0.200 ГГц; Сопротивление обмотки постоянноми току, не более: 2.38 Ом; Допустимый ток обмотки: 150 мА; Диапазон рабочих температур: от -60 до +125 ℃; Упаковка: Катушка и лента; Типоразмер: 2012 (0805); Технология монтажа: SMT; Изготовитель: АО "НПО "ЭРКОН"
footprint КИК-2012-Зл (Катушка индуктивности с керамическим сердечникомтипоразмер 2012(0805))
pins: 1, 2

## КИК-2012-1200 нГн ±10% O
designator L?, comment 1200 нГн ±5%  (value not drawn)
Катушка индуктивности с керамическим сердечником и  финишным покрытием контактных площадок оловом; Допускаемое отклонение индуктивности: ±10%; Добротность, не менее: 17; Резонансная частота, не менее: 0.200 ГГц; Сопротивление обмотки постоянноми току, не более: 2.38 Ом; Допустимый ток обмотки: 150 мА; Диапазон рабочих температур: от -60 до +125 ℃; Упаковка: Катушка и лента; Типоразмер: 2012 (0805); Технология монтажа: SMT; Изготовитель: АО "НПО "ЭРКОН"
footprint КИК-2012-O (Катушка индуктивности с керамическим сердечником типоразмер 2012(0805))
pins: 1, 2

## КИК-2012-1200 нГн ±10% Зл
designator L?, comment 1200 нГн ±5%  (value not drawn)
Катушка индуктивности с керамическим сердечником и золотым покрытием контактных площадок; Допускаемое отклонение индуктивности: ±10%; Добротность, не менее: 17; Резонансная частота, не менее: 0.200 ГГц; Сопротивление обмотки постоянноми току, не более: 2.38 Ом; Допустимый ток обмотки: 150 мА; Диапазон рабочих температур: от -60 до +125 ℃; Упаковка: Катушка и лента; Типоразмер: 2012 (0805); Технология монтажа: SMT; Изготовитель: АО "НПО "ЭРКОН"
footprint КИК-2012-Зл (Катушка индуктивности с керамическим сердечникомтипоразмер 2012(0805))
pins: 1, 2

## КИК-2012-1500 нГн ±5% O
designator L?, comment 1500 нГн ±5%  (value not drawn)
Катушка индуктивности с керамическим сердечником и  финишным покрытием контактных площадок оловом; Добротность, не менее: 17; Резонансная частота, не менее: 0.180 ГГц; Сопротивление обмотки постоянноми току, не более: 2.9 Ом; Допустимый ток обмотки: 130 мА; Диапазон рабочих температур: от -60 до +125 ℃; Упаковка: Катушка и лента; Типоразмер: 2012 (0805); Технология монтажа: SMT; Изготовитель: АО "НПО "ЭРКОН"
footprint КИК-2012-O (Катушка индуктивности с керамическим сердечником типоразмер 2012(0805))
pins: 1, 2

## КИК-2012-1500 нГн ±5% Зл
designator L?, comment 1500 нГн ±5%  (value not drawn)
Катушка индуктивности с керамическим сердечником и золотым покрытием контактных площадок; Добротность, не менее: 17; Резонансная частота, не менее: 0.180 ГГц; Сопротивление обмотки постоянноми току, не более: 2.9 Ом; Допустимый ток обмотки: 130 мА; Диапазон рабочих температур: от -60 до +125 ℃; Упаковка: Катушка и лента; Типоразмер: 2012 (0805); Технология монтажа: SMT; Изготовитель: АО "НПО "ЭРКОН"
footprint КИК-2012-Зл (Катушка индуктивности с керамическим сердечникомтипоразмер 2012(0805))
pins: 1, 2

## КИК-2012-1500 нГн ±10% O
designator L?, comment 1500 нГн ±10%  (value not drawn)
Катушка индуктивности с керамическим сердечником и  финишным покрытием контактных площадок оловом; Добротность, не менее: 17; Резонансная частота, не менее: 0.180 ГГц; Сопротивление обмотки постоянноми току, не более: 2.9 Ом; Допустимый ток обмотки: 130 мА; Диапазон рабочих температур: от -60 до +125 ℃; Упаковка: Катушка и лента; Типоразмер: 2012 (0805); Технология монтажа: SMT; Изготовитель: АО "НПО "ЭРКОН"
footprint КИК-2012-O (Катушка индуктивности с керамическим сердечником типоразмер 2012(0805))
pins: 1, 2

## КИК-2012-1500 нГн ±10% Зл
designator L?, comment 1500 нГн ±10%  (value not drawn)
Катушка индуктивности с керамическим сердечником и золотым покрытием контактных площадок; Добротность, не менее: 17; Резонансная частота, не менее: 0.180 ГГц; Сопротивление обмотки постоянноми току, не более: 2.9 Ом; Допустимый ток обмотки: 130 мА; Диапазон рабочих температур: от -60 до +125 ℃; Упаковка: Катушка и лента; Типоразмер: 2012 (0805); Технология монтажа: SMT; Изготовитель: АО "НПО "ЭРКОН"
footprint КИК-2012-Зл (Катушка индуктивности с керамическим сердечникомтипоразмер 2012(0805))
pins: 1, 2

## КИК-2012-1800 нГн ±5% O
designator L?, comment 1800 нГн ±5%  (value not drawn)
Катушка индуктивности с керамическим сердечником и  финишным покрытием контактных площадок оловом; Добротность, не менее: 17; Резонансная частота, не менее: 0.120 ГГц; Сопротивление обмотки постоянноми току, не более: 3 Ом; Допустимый ток обмотки: 120 мА; Диапазон рабочих температур: от -60 до +125 ℃; Упаковка: Катушка и лента; Типоразмер: 2012 (0805); Технология монтажа: SMT; Изготовитель: АО "НПО "ЭРКОН"
footprint КИК-2012-O (Катушка индуктивности с керамическим сердечником типоразмер 2012(0805))
pins: 1, 2

## КИК-2012-1800 нГн ±5% Зл
designator L?, comment 1800 нГн ±5%  (value not drawn)
Катушка индуктивности с керамическим сердечником и золотым покрытием контактных площадок; Добротность, не менее: 17; Резонансная частота, не менее: 0.120 ГГц; Сопротивление обмотки постоянноми току, не более: 3 Ом; Допустимый ток обмотки: 120 мА; Диапазон рабочих температур: от -60 до +125 ℃; Упаковка: Катушка и лента; Типоразмер: 2012 (0805); Технология монтажа: SMT; Изготовитель: АО "НПО "ЭРКОН"
footprint КИК-2012-Зл (Катушка индуктивности с керамическим сердечникомтипоразмер 2012(0805))
pins: 1, 2

## КИК-2012-1800 нГн ±10% O
designator L?, comment 1800 нГн ±10%  (value not drawn)
Катушка индуктивности с керамическим сердечником и  финишным покрытием контактных площадок оловом; Добротность, не менее: 17; Резонансная частота, не менее: 0.120 ГГц; Сопротивление обмотки постоянноми току, не более: 3 Ом; Допустимый ток обмотки: 120 мА; Диапазон рабочих температур: от -60 до +125 ℃; Упаковка: Катушка и лента; Типоразмер: 2012 (0805); Технология монтажа: SMT; Изготовитель: АО "НПО "ЭРКОН"
footprint КИК-2012-O (Катушка индуктивности с керамическим сердечником типоразмер 2012(0805))
pins: 1, 2

## КИК-2012-2200 нГн ±5% O
designator L?, comment 2200 нГн ±5%  (value not drawn)
Катушка индуктивности с керамическим сердечником и  финишным покрытием контактных площадок оловом; Добротность, не менее: 17; Резонансная частота, не менее: 0.110 ГГц; Сопротивление обмотки постоянноми току, не более: 3.1 Ом; Допустимый ток обмотки: 110 мА; Диапазон рабочих температур: от -60 до +125 ℃; Упаковка: Катушка и лента; Типоразмер: 2012 (0805); Технология монтажа: SMT; Изготовитель: АО "НПО "ЭРКОН"
footprint КИК-2012-O (Катушка индуктивности с керамическим сердечником типоразмер 2012(0805))
pins: 1, 2

## КИК-2012-2200 нГн ±5% Зл
designator L?, comment 2200 нГн ±5%  (value not drawn)
Катушка индуктивности с керамическим сердечником и золотым покрытием контактных площадок; Добротность, не менее: 17; Резонансная частота, не менее: 0.110 ГГц; Сопротивление обмотки постоянноми току, не более: 3.1 Ом; Допустимый ток обмотки: 110 мА; Диапазон рабочих температур: от -60 до +125 ℃; Упаковка: Катушка и лента; Типоразмер: 2012 (0805); Технология монтажа: SMT; Изготовитель: АО "НПО "ЭРКОН"
footprint КИК-2012-Зл (Катушка индуктивности с керамическим сердечникомтипоразмер 2012(0805))
pins: 1, 2

## КИК-2012-2200 нГн ±10% O
designator L?, comment 2200 нГн ±10%  (value not drawn)
Катушка индуктивности с керамическим сердечником и  финишным покрытием контактных площадок оловом; Добротность, не менее: 17; Резонансная частота, не менее: 0.110 ГГц; Сопротивление обмотки постоянноми току, не более: 3.1 Ом; Допустимый ток обмотки: 110 мА; Диапазон рабочих температур: от -60 до +125 ℃; Упаковка: Катушка и лента; Типоразмер: 2012 (0805); Технология монтажа: SMT; Изготовитель: АО "НПО "ЭРКОН"
footprint КИК-2012-O (Катушка индуктивности с керамическим сердечником типоразмер 2012(0805))
pins: 1, 2

## КИК-2012-2200 нГн ±10% Зл
designator L?, comment 2200 нГн ±10%  (value not drawn)
Катушка индуктивности с керамическим сердечником и золотым покрытием контактных площадок; Добротность, не менее: 17; Резонансная частота, не менее: 0.11 ГГц; Сопротивление обмотки постоянноми току, не более: 3.1 Ом; Допустимый ток обмотки: 110 мА; Диапазон рабочих температур: от -60 до +125 ℃; Упаковка: Катушка и лента; Типоразмер: 2012 (0805); Технология монтажа: SMT; Изготовитель: АО "НПО "ЭРКОН"
footprint КИК-2012-Зл (Катушка индуктивности с керамическим сердечникомтипоразмер 2012(0805))
pins: 1, 2

## КИК-2012-3900 нГн ±5% O
designator L?, comment 3900 нГн ±5%  (value not drawn)
Катушка индуктивности с керамическим сердечником и  финишным покрытием контактных площадок оловом; Добротность, не менее: 17; Резонансная частота, не менее: 0.070 ГГц; Сопротивление обмотки постоянноми току, не более: 4.5 Ом; Допустимый ток обмотки: 75 мА; Диапазон рабочих температур: от -60 до +125 ℃; Упаковка: Катушка и лента; Типоразмер: 2012 (0805); Технология монтажа: SMT; Изготовитель: АО "НПО "ЭРКОН"
footprint КИК-2012-O (Катушка индуктивности с керамическим сердечником типоразмер 2012(0805))
pins: 1, 2

## КИК-2012-3900 нГн ±5% Зл
designator L?, comment 3900 нГн ±5%  (value not drawn)
Катушка индуктивности с керамическим сердечником и золотым покрытием контактных площадок; Добротность, не менее: 17; Резонансная частота, не менее: 0.070 ГГц; Сопротивление обмотки постоянноми току, не более: 4.5 Ом; Допустимый ток обмотки: 75 мА; Диапазон рабочих температур: от -60 до +125 ℃; Упаковка: Катушка и лента; Типоразмер: 2012 (0805); Технология монтажа: SMT; Изготовитель: АО "НПО "ЭРКОН"
footprint КИК-2012-Зл (Катушка индуктивности с керамическим сердечникомтипоразмер 2012(0805))
pins: 1, 2

## КИК-2012-3900 нГн ±10% O
designator L?, comment 3900 нГн ±10%  (value not drawn)
Катушка индуктивности с керамическим сердечником и  финишным покрытием контактных площадок оловом; Добротность, не менее: 17; Резонансная частота, не менее: 0.070 ГГц; Сопротивление обмотки постоянноми току, не более: 4.5 Ом; Допустимый ток обмотки: 75 мА; Диапазон рабочих температур: от -60 до +125 ℃; Упаковка: Катушка и лента; Типоразмер: 2012 (0805); Технология монтажа: SMT; Изготовитель: АО "НПО "ЭРКОН"
footprint КИК-2012-O (Катушка индуктивности с керамическим сердечником типоразмер 2012(0805))
pins: 1, 2

## КИК-2012-3900 нГн ±10% Зл
designator L?, comment 3900 нГн ±10%  (value not drawn)
Катушка индуктивности с керамическим сердечником и золотым покрытием контактных площадок; Добротность, не менее: 17; Резонансная частота, не менее: 0.070 ГГц; Сопротивление обмотки постоянноми току, не более: 4.5 Ом; Допустимый ток обмотки: 75 мА; Диапазон рабочих температур: от -60 до +125 ℃; Упаковка: Катушка и лента; Типоразмер: 2012 (0805); Технология монтажа: SMT; Изготовитель: АО "НПО "ЭРКОН"
footprint КИК-2012-Зл (Катушка индуктивности с керамическим сердечникомтипоразмер 2012(0805))
pins: 1, 2

## КИК-2012-4700 нГн ±5% O
designator L?, comment 4700 нГн ±5%  (value not drawn)
Катушка индуктивности с керамическим сердечником и  финишным покрытием контактных площадок оловом; Добротность, не менее: 17; Резонансная частота, не менее: 0.065 ГГц; Сопротивление обмотки постоянноми току, не более: 5 Ом; Допустимый ток обмотки: 50 мА; Диапазон рабочих температур: от -60 до +125 ℃; Упаковка: Катушка и лента; Типоразмер: 2012 (0805); Технология монтажа: SMT; Изготовитель: АО "НПО "ЭРКОН"
footprint КИК-2012-O (Катушка индуктивности с керамическим сердечником типоразмер 2012(0805))
pins: 1, 2

## КИК-2012-4700 нГн ±5% Зл
designator L?, comment 4700 нГн ±5%  (value not drawn)
Катушка индуктивности с керамическим сердечником и золотым покрытием контактных площадок; Добротность, не менее: 17; Резонансная частота, не менее: 0.065 ГГц; Сопротивление обмотки постоянноми току, не более: 5 Ом; Допустимый ток обмотки: 50 мА; Диапазон рабочих температур: от -60 до +125 ℃; Упаковка: Катушка и лента; Типоразмер: 2012 (0805); Технология монтажа: SMT; Изготовитель: АО "НПО "ЭРКОН"
footprint КИК-2012-Зл (Катушка индуктивности с керамическим сердечникомтипоразмер 2012(0805))
pins: 1, 2

## КИК-2012-4700 нГн ±10% O
designator L?, comment 4700 нГн ±10%  (value not drawn)
Катушка индуктивности с керамическим сердечником и  финишным покрытием контактных площадок оловом; Добротность, не менее: 17; Резонансная частота, не менее: 0.065 ГГц; Сопротивление обмотки постоянноми току, не более: 5 Ом; Допустимый ток обмотки: 50 мА; Диапазон рабочих температур: от -60 до +125 ℃; Упаковка: Катушка и лента; Типоразмер: 2012 (0805); Технология монтажа: SMT; Изготовитель: АО "НПО "ЭРКОН"
footprint КИК-2012-O (Катушка индуктивности с керамическим сердечником типоразмер 2012(0805))
pins: 1, 2

## КИК-2012-4700 нГн ±10% Зл
designator L?, comment 4700 нГн ±10%  (value not drawn)
Катушка индуктивности с керамическим сердечником и золотым покрытием контактных площадок; Добротность, не менее: 17; Резонансная частота, не менее: 0.065 ГГц; Сопротивление обмотки постоянноми току, не более: 5 Ом; Допустимый ток обмотки: 50 мА; Диапазон рабочих температур: от -60 до +125 ℃; Упаковка: Катушка и лента; Типоразмер: 2012 (0805); Технология монтажа: SMT; Изготовитель: АО "НПО "ЭРКОН"
footprint КИК-2012-Зл (Катушка индуктивности с керамическим сердечникомтипоразмер 2012(0805))
pins: 1, 2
